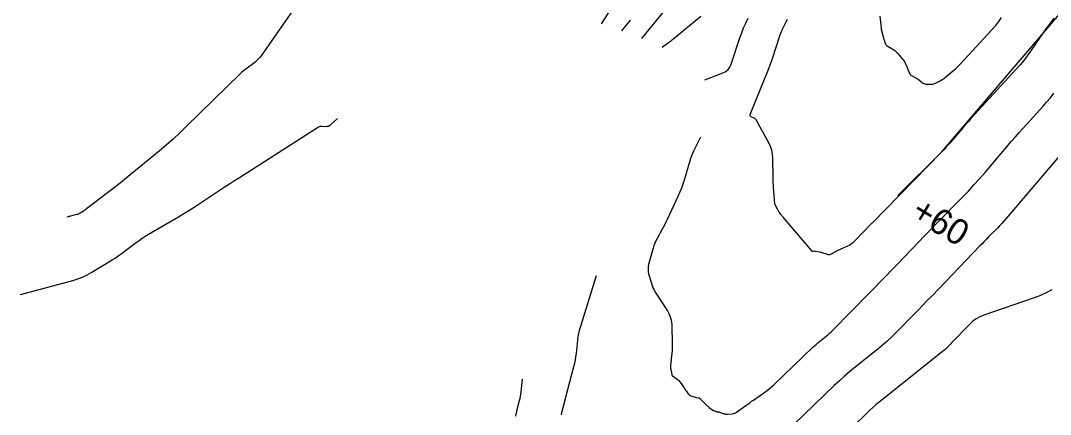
# Model space of a CAD drawing. Extents: x 1005228 to 1008882, y 1883389 to 1885754.
# Drawn here: x 1007264.5 to 1007516.7, y 1884595.8 to 1884692.1 of the extents above; entities that cross this region are included whole.
import ezdxf

# ---------------------------------------------------------------- set-up
doc = ezdxf.new("R2010")
doc.units = 0
for name, color, linetype in [('C-ANNO-NOTE', 7, 'Continuous'), ('R_Erosion', 7, 'Continuous'), ('S_BASELINE', 7, 'Continuous'), ('S_BRIDGE', 7, 'Continuous')]:
    doc.layers.add(name, color=color, linetype=linetype)

msp = doc.modelspace()

# ---------------------------------------------------------------- linework, layer by layer
at = {"layer": 'C-ANNO-NOTE'}
for points in [[(1007337.01, 1884703.14), (1007323.41, 1884683.54), (1007323.06, 1884683.08), (1007322.68, 1884682.65), (1007322.26, 1884682.25), (1007321.81, 1884681.89), (1007319.93, 1884680.51), (1007319.46, 1884680.15), (1007319.01, 1884679.78), (1007318.58, 1884679.4), (1007318.15, 1884679), (1007305.06, 1884666.19), (1007303.45, 1884664.64), (1007301.8, 1884663.13), (1007300.12, 1884661.65), (1007298.4, 1884660.21), (1007289.91, 1884653.24), (1007288.96, 1884652.47), (1007288.01, 1884651.71), (1007287.05, 1884650.95), (1007286.08, 1884650.21), (1007280.63, 1884646.06), (1007280.44, 1884645.92), (1007280.24, 1884645.78), (1007280.05, 1884645.65), (1007279.85, 1884645.53), (1007279.04, 1884645.04), (1007278.83, 1884644.92), (1007278.62, 1884644.82), (1007278.41, 1884644.74), (1007278.18, 1884644.67), (1007275.81, 1884644.04)], [(1007406.77, 1884691.34), (1007409.16, 1884695.04)], [(1007422.72, 1884695.26), (1007416.54, 1884687.77)], [(1007411.75, 1884689.6), (1007413.9, 1884692.21)], [(1007432.09, 1884677.65), (1007436.53, 1884679.36), (1007437.21, 1884679.7), (1007437.77, 1884680.16), (1007438.21, 1884680.74), (1007438.52, 1884681.44), (1007440.68, 1884687.88), (1007441.11, 1884689.11), (1007441.59, 1884690.33), (1007442.1, 1884691.53), (1007442.66, 1884692.72)], [(1007517.6, 1884692.71), (1007516.72, 1884691.61), (1007515.87, 1884690.47), (1007515.05, 1884689.32), (1007511.86, 1884684.64), (1007511.05, 1884683.48), (1007510.19, 1884682.36), (1007509.29, 1884681.27), (1007508.35, 1884680.21), (1007497.28, 1884668.14), (1007496.66, 1884667.47), (1007496.06, 1884666.79), (1007495.46, 1884666.11), (1007494.87, 1884665.42), (1007492.51, 1884662.66), (1007491.92, 1884661.97), (1007491.31, 1884661.3), (1007490.69, 1884660.63), (1007490.06, 1884659.98), (1007473.04, 1884642.62), (1007472.91, 1884642.49), (1007472.78, 1884642.36), (1007472.66, 1884642.23), (1007472.54, 1884642.1), (1007472.04, 1884641.59), (1007471.91, 1884641.46), (1007471.79, 1884641.33), (1007471.66, 1884641.2), (1007471.54, 1884641.07), (1007468.3, 1884637.77), (1007468.02, 1884637.52), (1007467.72, 1884637.29), (1007467.4, 1884637.09), (1007467.06, 1884636.93), (1007465.57, 1884636.29), (1007465.26, 1884636.16), (1007464.96, 1884636.02), (1007464.66, 1884635.87), (1007464.36, 1884635.71), (1007463.04, 1884634.99), (1007462.82, 1884634.9), (1007462.59, 1884634.85), (1007462.35, 1884634.86), (1007462.11, 1884634.92), (1007461.03, 1884635.28), (1007460.85, 1884635.34), (1007460.67, 1884635.39), (1007460.48, 1884635.44), (1007460.29, 1884635.47), (1007459.19, 1884635.68), (1007459.16, 1884635.68), (1007459.13, 1884635.69), (1007459.06, 1884635.7), (1007459.05, 1884635.7), (1007459.03, 1884635.7), (1007459.01, 1884635.7), (1007459, 1884635.7), (1007458.63, 1884635.64), (1007458.56, 1884635.64), (1007458.5, 1884635.65), (1007458.45, 1884635.68), (1007458.4, 1884635.73), (1007451.3, 1884644.02), (1007451.17, 1884644.17), (1007451.05, 1884644.32), (1007450.92, 1884644.47), (1007450.8, 1884644.63), (1007450.32, 1884645.25), (1007450.2, 1884645.41), (1007450.1, 1884645.58), (1007450, 1884645.74), (1007449.91, 1884645.92), (1007449.24, 1884647.31), (1007449.23, 1884647.32), (1007449.23, 1884647.32), (1007449.23, 1884647.38), (1007449.23, 1884647.41), (1007449.23, 1884647.43), (1007448.94, 1884651.27), (1007448.9, 1884651.91), (1007448.86, 1884652.56), (1007448.84, 1884653.2), (1007448.82, 1884653.85), (1007448.76, 1884658.51), (1007448.68, 1884659.49), (1007448.49, 1884660.43), (1007448.19, 1884661.35), (1007447.77, 1884662.23), (1007444.75, 1884667.72), (1007444.64, 1884667.89), (1007444.5, 1884668.04), (1007444.35, 1884668.16), (1007444.17, 1884668.26), (1007443.41, 1884668.62), (1007443.25, 1884668.72), (1007443.16, 1884668.85), (1007443.14, 1884669), (1007443.19, 1884669.18), (1007446.9, 1884678.24), (1007447.34, 1884679.33), (1007447.76, 1884680.42), (1007448.16, 1884681.53), (1007448.54, 1884682.63), (1007450.46, 1884688.36), (1007450.62, 1884688.83), (1007450.81, 1884689.29), (1007451, 1884689.75), (1007451.21, 1884690.2), (1007452.08, 1884691.98), (1007452.3, 1884692.43)], [(1007474.92, 1884693.17), (1007475.25, 1884690.29), (1007475.25, 1884690.26), (1007475.26, 1884690.24), (1007475.26, 1884690.22), (1007475.26, 1884690.19), (1007475.26, 1884690.1), (1007475.26, 1884690.08), (1007475.26, 1884690.06), (1007475.26, 1884690.04), (1007475.27, 1884690.02), (1007475.92, 1884687.62), (1007475.97, 1884687.47), (1007476.01, 1884687.32), (1007476.06, 1884687.17), (1007476.12, 1884687.02), (1007476.34, 1884686.43), (1007476.4, 1884686.29), (1007476.49, 1884686.17), (1007476.59, 1884686.06), (1007476.71, 1884685.97), (1007478.35, 1884684.95), (1007478.62, 1884684.77), (1007478.88, 1884684.56), (1007479.13, 1884684.33), (1007479.35, 1884684.08), (1007480.61, 1884682.57), (1007480.63, 1884682.54), (1007480.65, 1884682.52), (1007480.68, 1884682.5), (1007480.7, 1884682.48), (1007480.81, 1884682.39), (1007480.83, 1884682.37), (1007480.85, 1884682.34), (1007480.87, 1884682.32), (1007480.88, 1884682.29), (1007481.55, 1884680.81), (1007481.63, 1884680.62), (1007481.72, 1884680.43), (1007481.8, 1884680.23), (1007481.88, 1884680.04), (1007482.2, 1884679.25), (1007482.29, 1884679.07), (1007482.41, 1884678.91), (1007482.55, 1884678.77), (1007482.73, 1884678.66), (1007484.32, 1884677.82), (1007484.33, 1884677.82), (1007484.33, 1884677.82), (1007484.34, 1884677.81), (1007484.34, 1884677.81), (1007484.36, 1884677.82), (1007484.36, 1884677.82), (1007484.36, 1884677.81), (1007484.37, 1884677.81), (1007484.37, 1884677.81), (1007485.4, 1884676.93), (1007485.58, 1884676.8), (1007485.77, 1884676.71), (1007485.97, 1884676.64), (1007486.19, 1884676.61), (1007487.4, 1884676.55), (1007487.67, 1884676.55), (1007487.94, 1884676.59), (1007488.2, 1884676.66), (1007488.45, 1884676.77), (1007489.93, 1884677.51), (1007490.26, 1884677.69), (1007490.57, 1884677.88), (1007490.87, 1884678.1), (1007491.16, 1884678.33), (1007493.07, 1884679.97), (1007493.48, 1884680.33), (1007493.87, 1884680.7), (1007494.26, 1884681.08), (1007494.63, 1884681.47), (1007503.33, 1884690.95), (1007503.53, 1884691.18), (1007503.72, 1884691.41), (1007503.9, 1884691.64), (1007504.07, 1884691.89), (1007504.74, 1884692.87)], [(1007431.01, 1884663.65), (1007429.33, 1884660.18), (1007429.06, 1884659.6), (1007428.81, 1884659.01), (1007428.59, 1884658.41), (1007428.4, 1884657.8), (1007426.99, 1884653.11), (1007426.68, 1884652.13), (1007426.33, 1884651.16), (1007425.95, 1884650.21), (1007425.54, 1884649.27), (1007422.84, 1884643.44), (1007422.56, 1884642.85), (1007422.28, 1884642.27), (1007421.98, 1884641.7), (1007421.67, 1884641.13), (1007420.41, 1884638.86), (1007420.11, 1884638.29), (1007419.85, 1884637.7), (1007419.62, 1884637.1), (1007419.43, 1884636.48), (1007418.31, 1884632.48), (1007418.2, 1884631.9), (1007418.16, 1884631.33), (1007418.2, 1884630.76), (1007418.32, 1884630.18), (1007418.98, 1884627.89), (1007419.16, 1884627.33), (1007419.38, 1884626.78), (1007419.65, 1884626.25), (1007419.95, 1884625.74), (1007422.91, 1884621.12), (1007423.37, 1884620.3), (1007423.7, 1884619.44), (1007423.91, 1884618.55), (1007423.99, 1884617.62), (1007424.1, 1884613.05), (1007424.11, 1884612.48), (1007424.09, 1884611.9), (1007424.06, 1884611.33), (1007424.01, 1884610.75), (1007423.7, 1884607.76), (1007423.69, 1884607.54), (1007423.69, 1884607.31), (1007423.7, 1884607.09), (1007423.74, 1884606.87), (1007423.97, 1884605.57), (1007423.98, 1884605.55), (1007423.98, 1884605.52), (1007423.99, 1884605.5), (1007423.99, 1884605.48), (1007424, 1884605.39), (1007424.01, 1884605.36), (1007424.01, 1884605.34), (1007424.03, 1884605.33), (1007424.04, 1884605.31), (1007425.32, 1884604.42), (1007425.54, 1884604.26), (1007425.73, 1884604.08), (1007425.9, 1884603.88), (1007426.06, 1884603.67), (1007426.98, 1884602.3), (1007427.11, 1884602.11), (1007427.23, 1884601.93), (1007427.36, 1884601.75), (1007427.48, 1884601.57), (1007428, 1884600.84), (1007428.13, 1884600.68), (1007428.29, 1884600.54), (1007428.46, 1884600.44), (1007428.66, 1884600.36), (1007429.71, 1884600.03), (1007429.8, 1884600), (1007429.9, 1884599.98), (1007430, 1884599.95), (1007430.1, 1884599.93), (1007430.49, 1884599.87), (1007430.59, 1884599.84), (1007430.68, 1884599.81), (1007430.76, 1884599.76), (1007430.84, 1884599.69), (1007432.51, 1884598.09), (1007432.67, 1884597.94), (1007432.83, 1884597.8), (1007433, 1884597.66), (1007433.17, 1884597.53), (1007434.02, 1884596.88), (1007434.11, 1884596.82), (1007434.21, 1884596.76), (1007434.31, 1884596.71), (1007434.41, 1884596.67), (1007434.92, 1884596.5), (1007434.99, 1884596.48), (1007435.05, 1884596.46), (1007435.12, 1884596.45), (1007435.19, 1884596.44), (1007435.46, 1884596.41), (1007435.53, 1884596.4), (1007435.6, 1884596.38), (1007435.67, 1884596.37), (1007435.73, 1884596.35), (1007436.77, 1884595.98), (1007436.96, 1884595.92), (1007437.16, 1884595.88), (1007437.36, 1884595.87), (1007437.56, 1884595.87), (1007438.84, 1884595.97), (1007439.11, 1884596.01), (1007439.37, 1884596.09), (1007439.62, 1884596.2), (1007439.86, 1884596.34), (1007442.16, 1884598.02), (1007442.62, 1884598.35), (1007443.09, 1884598.68), (1007443.55, 1884599.01), (1007444.02, 1884599.33), (1007446.76, 1884601.23), (1007447.37, 1884601.67), (1007447.95, 1884602.12), (1007448.52, 1884602.61), (1007449.07, 1884603.11), (1007458.55, 1884612.22), (1007458.94, 1884612.59), (1007459.34, 1884612.94), (1007459.74, 1884613.29), (1007460.15, 1884613.63), (1007461.82, 1884614.96), (1007462.23, 1884615.3), (1007462.63, 1884615.65), (1007463.02, 1884616.01), (1007463.4, 1884616.38), (1007476.63, 1884629.86), (1007477.64, 1884630.89), (1007478.65, 1884631.93), (1007479.65, 1884632.96), (1007480.65, 1884634), (1007484.66, 1884638.16), (1007485.66, 1884639.2), (1007486.66, 1884640.23), (1007487.67, 1884641.27), (1007488.68, 1884642.3), (1007495.22, 1884648.97), (1007496.64, 1884650.44), (1007498.02, 1884651.93), (1007499.39, 1884653.44), (1007500.72, 1884654.98), (1007507.22, 1884662.61), (1007508.16, 1884663.69), (1007509.1, 1884664.76), (1007510.05, 1884665.83), (1007511.01, 1884666.88), (1007514.87, 1884671.09), (1007515.82, 1884672.16), (1007516.72, 1884673.26), (1007517.59, 1884674.39)], [(1007517.1, 1884626.31), (1007515.7, 1884625.57), (1007514.27, 1884624.92), (1007512.79, 1884624.36), (1007500.45, 1884620.08), (1007499.46, 1884619.67), (1007498.53, 1884619.15), (1007497.68, 1884618.53), (1007496.89, 1884617.8), (1007492.7, 1884613.45), (1007492.54, 1884613.28), (1007492.37, 1884613.11), (1007492.21, 1884612.94), (1007492.04, 1884612.77), (1007491.37, 1884612.09), (1007491.2, 1884611.92), (1007491.03, 1884611.76), (1007490.85, 1884611.6), (1007490.67, 1884611.45), (1007474.81, 1884598.8), (1007474, 1884598.14), (1007473.2, 1884597.46), (1007472.42, 1884596.76), (1007471.66, 1884596.04), (1007468.63, 1884593.13)], [(1007385.76, 1884595.34), (1007385.87, 1884595.89), (1007385.99, 1884596.44), (1007386.13, 1884596.99), (1007386.72, 1884599.23), (1007386.85, 1884599.74), (1007386.95, 1884600.25), (1007387.03, 1884600.77), (1007387.1, 1884601.29), (1007387.41, 1884604.43)]]:
    msp.add_lwpolyline(points, dxfattribs=at)
at = {"layer": 'R_Erosion'}
msp.add_lwpolyline([(1007479.35, 1884649.35), (1007490.06, 1884659.98), (1007582.04, 1884767.38), (1007608.23, 1884786.44), (1007622.73, 1884788.72), (1007640.54, 1884783.01), (1007724.67, 1884699.7), (1007740.7, 1884720.15)], dxfattribs=at)
at = {"layer": 'S_BRIDGE'}
for points in [[(1007431.09, 1884693.15), (1007424.2, 1884687.43), (1007423.95, 1884687.23), (1007423.7, 1884687.03), (1007423.44, 1884686.84), (1007423.18, 1884686.65), (1007421.62, 1884685.53)], [(1007264.46, 1884625.15), (1007277.25, 1884628.58), (1007278.46, 1884628.95), (1007279.64, 1884629.4), (1007280.78, 1884629.94), (1007281.89, 1884630.56), (1007286.86, 1884633.58), (1007287.64, 1884634.06), (1007288.39, 1884634.56), (1007289.14, 1884635.08), (1007289.87, 1884635.63), (1007292.77, 1884637.83), (1007293.51, 1884638.37), (1007294.25, 1884638.89), (1007295.02, 1884639.39), (1007295.8, 1884639.86), (1007303.18, 1884644.16), (1007304.45, 1884644.91), (1007305.71, 1884645.68), (1007306.96, 1884646.47), (1007308.2, 1884647.28), (1007313.13, 1884650.55), (1007314.36, 1884651.37), (1007315.6, 1884652.18), (1007316.84, 1884652.98), (1007318.08, 1884653.78), (1007337.17, 1884666.01), (1007337.42, 1884666.14), (1007337.68, 1884666.24), (1007337.94, 1884666.29), (1007338.22, 1884666.3), (1007339.37, 1884666.26), (1007339.64, 1884666.28), (1007339.9, 1884666.34), (1007340.14, 1884666.46), (1007340.37, 1884666.62), (1007342.11, 1884668.16)], [(1007521.81, 1884662.41), (1007505.81, 1884643.65), (1007505.31, 1884643.07), (1007504.8, 1884642.5), (1007504.28, 1884641.94), (1007503.75, 1884641.39), (1007501.6, 1884639.21), (1007501.07, 1884638.66), (1007500.53, 1884638.11), (1007500, 1884637.56), (1007499.47, 1884637.01), (1007487.66, 1884624.74), (1007486.58, 1884623.63), (1007485.51, 1884622.52), (1007484.43, 1884621.41), (1007483.35, 1884620.31), (1007479.01, 1884615.89), (1007477.91, 1884614.81), (1007476.78, 1884613.76), (1007475.62, 1884612.74), (1007474.43, 1884611.76), (1007468.9, 1884607.34), (1007467.58, 1884606.27), (1007466.3, 1884605.17), (1007465.04, 1884604.04), (1007463.8, 1884602.88), (1007453.91, 1884593.38)], [(1007396.93, 1884595.71), (1007397.04, 1884596.26), (1007400.03, 1884607.53), (1007400.22, 1884608.32), (1007400.38, 1884609.12), (1007400.51, 1884609.93), (1007400.61, 1884610.74), (1007400.94, 1884613.99), (1007401.04, 1884614.8), (1007401.19, 1884615.6), (1007401.37, 1884616.4), (1007401.59, 1884617.18), (1007405.51, 1884629.75)]]:
    msp.add_lwpolyline(points, dxfattribs=at)

# ---------------------------------------------------------------- texts
at = {"layer": 'S_BASELINE'}
msp.add_text('+60', height=6.25, rotation=328.991, dxfattribs=at).set_placement((1007482.2, 1884643.99))

doc.saveas('drawing.dxf')
